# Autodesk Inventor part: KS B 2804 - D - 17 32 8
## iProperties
IsCustomPart: 0
Created: 2009-02
Part Number: KS B 2804 - D - 17 32 8
Material: 고무
Description: 오일-실
Document SubType Name: Modeling
Standard: KS B 2804
Designer: SeoGD™ [www.esajin.kr]
Standards Organization: KS
Language: ko-KR
Size Designation: D - 17 32 8
Categories: <MemberInstance><Categories><Category DisplayName="샤프트 부품" InternalName="7f7aeb1f-a693-4053-b835-cee3144e0d98" Mnemonic="SHFT"><Category DisplayName="실링" Intern
Density: 0.93 g/cm^3
Author: SeoGD™ [www.esajin.kr]
